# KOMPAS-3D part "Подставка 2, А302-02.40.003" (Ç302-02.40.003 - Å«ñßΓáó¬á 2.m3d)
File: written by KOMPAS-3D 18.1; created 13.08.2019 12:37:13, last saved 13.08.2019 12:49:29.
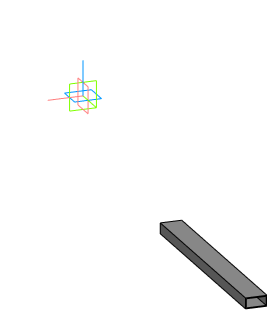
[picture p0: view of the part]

Document properties: Автор: Пользователь Windows; Полное имя файла: D:\Мембранные насосы\Мембранный электропривод\А302-00.00.000 - ASTRA-302 (МЭ200)\3Д ПВХ\А302-02.40.003 - Подставка 2.m3d

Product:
- Part/product: Подставка 2  | designation А302-02.40.003
    Масса: 0.564218

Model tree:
1. Эскиз:4  (labels: Мембранный насос@/ASTRA-302-PVC; Каркас\Подставка 2)
2. Элемент выдавливания:1
     Расстояние 1 = 77.5; Расстояние 2 = 342.5

Referenced files in D:\Мембранные насосы\Мембранный электропривод\А302-00.00.000 - ASTRA-302 (МЭ200)\3Д ПВХ\: А302-01.00.000  - Мембранный насос ASTRA-302 ПВХ.a3d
